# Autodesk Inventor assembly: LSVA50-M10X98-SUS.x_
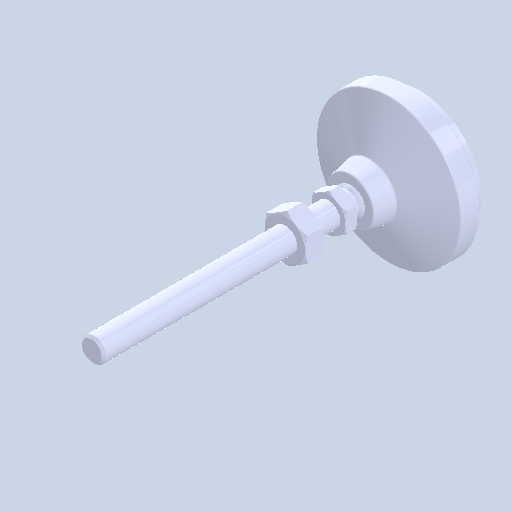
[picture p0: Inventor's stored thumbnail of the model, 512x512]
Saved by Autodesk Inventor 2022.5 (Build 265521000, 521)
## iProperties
Created: 2024-08
Part Number: LSVA50-M10X98-SUS.x_
Document SubType Name: Assembly
Designer: ImaoCorp
Author: ImaoCorp
Sending System: SOLIDWORKS 2022-2022290
MC: AMD64
MC_MODEL: Intel64 Family 6 Model 60 Stepping 3, GenuineIntel
OS: Windows_NT
FRU: Parasolid Version 33.1, build 260,  4-25-2022
FORMAT: text
GUISE: transmit
KEY: FILELSVA50-M10X98-SUS.x_t
DATE: Fri Aug 23 16:08:16 2024
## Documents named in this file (4)
- X:\14_SW2022-Inv2022\06_2024-10新製品(SME)\ELS_データ\l\lsva50-m10x98-sus\LSVA50-M10X98-SUS.x_.iam
- X:\14_SW2022-Inv2022\06_2024-10新製品(SME)\ELS_データ\l\lsva50-m10x98-sus\LSVA50-M10X98-SUS_01.ipt
- X:\14_SW2022-Inv2022\06_2024-10新製品(SME)\ELS_データ\l\lsva50-m10x98-sus\LSVA50-M10X98-SUS_02.ipt
- X:\14_SW2022-Inv2022\06_2024-10新製品(SME)\ELS_データ\l\lsva50-m10x98-sus\LSVA50-M10X98-SUS_03.ipt
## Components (3 placed, 3 different names)
1. LSVA50-M10X98-SUS_01
2. LSVA50-M10X98-SUS_02
3. LSVA50-M10X98-SUS_03
